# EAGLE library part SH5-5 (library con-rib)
RIBBON CABLE CONNECTOR Flachstecker / Faston
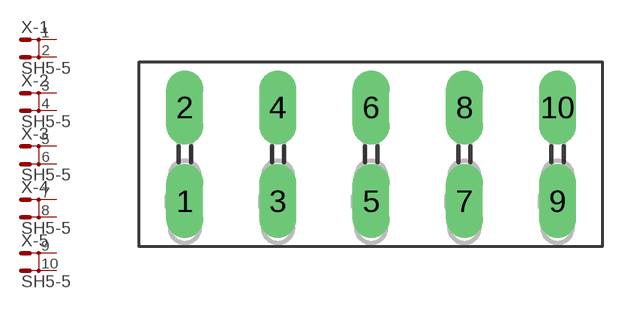
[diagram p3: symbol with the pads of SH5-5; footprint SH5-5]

Designator prefix X; gates -1=MD -2=MD -3=MD -4=MD -5=MD

## SH5-5  [SH5-5]
1  -1:1  pas
2  -1:2  pas
3  -2:1  pas
4  -2:2  pas
5  -3:1  pas
6  -3:2  pas
7  -4:1  pas
8  -4:2  pas
9  -5:1  pas
10  -5:2  pas

## Footprint SH5-5 (pad centres in mm)
RIBBON CABLE CONNECTOR Flachstecker / Faston
drill 1.321 long: 1 -10.008,-2.515; 2 -10.008,2.515; 3 -5.004,-2.515; 4 -5.004,2.515; 5 0,-2.515; 6 0,2.515; 7 5.004,-2.515; 8 5.004,2.515; 9 10.008,-2.515; 10 10.008,2.515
